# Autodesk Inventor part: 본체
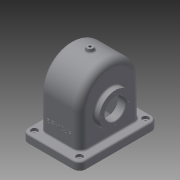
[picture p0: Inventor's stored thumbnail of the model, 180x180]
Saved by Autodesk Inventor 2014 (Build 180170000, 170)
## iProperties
Created: 2016-10
Part Number: 본체
Material: 일반
Document SubType Name: Modeling
Designer: USER
Density: 1 g/cm^3
Appearance: 기본값
Author: USER
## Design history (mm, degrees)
sketch "스케치1"
  geometry: L1 (43, -75)-(-43, -75); L2 (-55, -63)-(-55, 63); L3 (-43, 75)-(43, 75); L4 (55, 63)-(55, -63); L5 (55, -75)-(-55, 75); L6 (-55, -75)-(55, 75); A1 r 12 centre (-43, 63) between (-43, 75) and (-55, 63); A2 r 12 centre (43, 63) between (55, 63) and (43, 75); A3 r 12 centre (43, -63) between (43, -75) and (55, -63); A4 r 12 centre (-43, -63) between (-55, -63) and (-43, -75); 1 further point
  constraints: 12 end point, 8 point on circle, 8 point on line, 8 tangent, 4 centre point, 3 equal radius, 2 midpoint, 2 parallel, 1 horizontal, 1 perpendicular
  dimensions: "d0" = 110 distance of L5.end L6.end; "d1" = 150 distance of L6.end L5.start; "d2" = 12 radius of A1
extrude "돌출1" new body sketch "스케치1" distance "d3" = 15; taper "d4" = 0 deg
node "작업 평면1"
sketch "스케치2"
  geometry: L1 (0, -12)-(-15, -12) reference; L2 (-15, -12)-(-15, 138) reference; L3 (-15, 138)-(0, 138) reference; L4 (0, 138)-(0, -12) reference; L5 (-80, 5)-(-15, 5); L6 (-80, 121)-(-12.083, 121); L7 (-15, 5)-(-15, 121); C1 r 20 at (-65, 63); A1 r 58 centre (-80, 63) between (-80, 5) and (-80, 121); 2 further points
  constraints: 6 end point, 3 point on line, 2 centre point, 2 horizontal alignment, 2 perpendicular, 2 point on circle, 2 tangent, 1 midpoint
  dimensions: "d5" = 116 diameter of A1; "d6" = 80 distance of point (0, 63) A1.centre; "d7" = 40 diameter of C1; "d8" = 65 distance of point (0, 63) C1.centre
extrude "돌출2" join sketch "스케치2" stored distance "d9" = 77; taper "d10" = 0 deg
sketch "스케치3"
  geometry: L1 (0, -12)-(-15, -12) reference; L2 (-15, -12)-(-15, 5) reference; L3 (-15, 5)-(-80, 5) reference; L4 (-80, 121)-(-15, 121) reference; L5 (-15, 121)-(-15, 138) reference; L6 (-15, 138)-(0, 138) reference; L7 (0, 138)-(0, -12) reference; L8 (-80, 11)-(0, 11); L9 (0, 115)-(-80, 115); C1 r 20 at (-65, 63) reference; A1 r 58 centre (-80, 63) between (-80, 121) and (-80, 5) reference; A2 r 52 centre (-80, 63) between (-80, 115) and (-80, 11); 1 further point
  constraints: 4 end point, 2 point on circle, 2 point on line, 1 centre point
  dimensions: "d11" = 6 radial gap between concentric circles of A1 A2; "d12" = 104 distance between parallel lines of L9 L8; "d13" = 52 distance from line of C1.centre L9; "d14" = 80 distance of L9.start L9.end
extrude "돌출3" cut sketch "스케치3" stored distance "d15" = 67; taper "d16" = 0 deg
sketch "스케치4"
  geometry: C1 r 20 at (-65, 63) reference; C2 r 31 at (-65, 63); 1 further point
  constraints: 1 centre point, 1 coincident
  dimensions: "d17" = 62 diameter of C2
extrude "돌출4" join sketch "스케치4" distance "d18" = 10; taper "d19" = 0 deg
sketch "스케치5"
  geometry: C1 r 20 at (65, 63) reference; C2 r 37.5 at (65, 63); 1 further point
  constraints: 1 centre point, 1 coincident
  dimensions: "d20" = 75 diameter of C2
extrude "돌출5" join sketch "스케치5" distance "d21" = 5; taper "d22" = 0 deg
node "작업 평면2"
sketch "스케치6"
  geometry: L1 (-38.5, 138)-(38.5, 138) reference; L2 (38.5, 138)-(38.5, 102.5) reference; L3 (38.5, 102.5)-(43.5, 102.5) reference; L4 (43.5, 102.5)-(43.5, 85) reference; L5 (43.5, 85)-(33.5, 85) reference; L6 (33.5, 85)-(33.5, 132) reference; L7 (33.5, 132)-(-33.5, 132) reference; L8 (-33.5, 132)-(-33.5, 85) reference; L9 (-33.5, 85)-(-48.5, 85) reference; L10 (-48.5, 85)-(-48.5, 96) reference; L11 (-48.5, 96)-(-38.5, 96) reference; L12 (-38.5, 96)-(-38.5, 138) reference; L13 (-55, 0)-(-55, 15) reference; L14 (-55, 15)-(-38.5, 15) reference; L15 (-38.5, 15)-(-38.5, 34) reference; L16 (-38.5, 34)-(-48.5, 34) reference; L17 (-48.5, 34)-(-48.5, 45) reference; L18 (-48.5, 45)-(-33.5, 45) reference; L19 (-33.5, 45)-(-33.5, 0) reference; L20 (-33.5, 0)-(-55, 0) reference; L21 (55, 15)-(55, 0) reference; L22 (55, 0)-(33.5, 0) reference; L23 (33.5, 0)-(33.5, 45) reference; L24 (33.5, 45)-(43.5, 45) reference; L25 (43.5, 45)-(43.5, 27.5) reference; L26 (43.5, 27.5)-(38.5, 27.5) reference; L27 (38.5, 27.5)-(38.5, 15) reference; L28 (38.5, 15)-(55, 15) reference; L29 (43.5, 85)-(43.5, 45) reference; L30 (33.5, 85)-(33.5, 45) reference; L31 (43.5, 65)-(-28.801, 65); L32 (33.5, 104.747)-(19.5, 93); L33 (19.5, 93)-(19.5, 65); L34 (33.5, 104.747)-(33.5, 65); L35 (19.5, 65)-(33.5, 65); L36 (33.5, 85)-(19.5, 85); 1 further point
  constraints: 12 end point, 4 perpendicular, 4 point on line, 2 midpoint
  dimensions: "d24" = 56 diameter of L32.end L31; "d25" = 50 deg angle of L33 L32; "d26" = 24 distance between parallel lines of L29 L33
revolve "회전1" sketch "스케치6" stored, may be unused: angle "d27" = 90 deg
sketch "스케치7" dims "d28" = 52
  geometry: C1 r 20 at (0, 0) reference; C2 r 31 at (0, 0) reference; 6 further points
  constraints: 2 horizontal alignment, 1 coincident, 7 other
  dimensions: "d31" = 360 deg dimension on C1.centre point (-26, 0) (derived)
hole "구멍1" sketch "스케치7" at (-26, 0), (0, -26), (26, 0), (0, 26) diameter "d33" = 2.459; stored, may be unused: countersink angle "d37" = 90 deg, drill point angle "d39" = 118 deg; dims "d34" = 6, "d35" = 4, "d36" = 2, "d38" = 8
sketch "스케치8" dims "d40" = 58
  geometry: C1 r 20 at (0, 0) reference; C2 r 37.5 at (0, 0) reference; 6 further points
  constraints: 2 horizontal alignment, 1 coincident, 7 other
  dimensions: "d43" = 360 deg dimension on C1.centre point (29, 0) (derived)
hole "구멍2" sketch "스케치8" at (29, 0), (0, 29), (-29, 0), (0, -29) diameter "d45" = 2.459; stored, may be unused: countersink angle "d49" = 90 deg, drill point angle "d51" = 118 deg; dims "d46" = 6, "d47" = 4, "d48" = 2, "d50" = 8
sketch "스케치11"
  geometry: A1 r 12 centre (-43, -63) between (-55, -63) and (-43, -75) reference; A2 r 12 centre (43, -63) between (43, -75) and (55, -63) reference; A3 r 12 centre (43, 63) between (55, 63) and (43, 75) reference; A4 r 12 centre (-43, 63) between (-43, 75) and (-55, 63) reference; 5 further points
  constraints: 4 coincident
hole "구멍4" sketch "스케치11" at (-43, 63), (43, 63), (43, -63), (-43, -63) diameter "d64" = 5; stored, may be unused: countersink angle "d68" = 90 deg, drill point angle "d70" = 118 deg; dims "d65" = 40, "d66" = 12, "d67" = 5, "d69" = 50
fillet "모깎기1" dims "d71" = 8
fillet "모깎기2" dims "d72" = 13
sketch "스케치12"
  geometry: L1 (-48.5, 96)-(-38.5, 96) reference; L2 (-38.5, 96)-(-38.5, 125) reference; L3 (-25.5, 138)-(25.5, 138) reference; L4 (38.5, 125)-(38.5, 102.5) reference; L5 (38.5, 102.5)-(43.5, 102.5) reference; L6 (43.5, 102.5)-(43.5, 95.23) reference; L7 (43.5, 95.23)-(35.5, 95.23) reference; L8 (35.5, 95.23)-(34.761, 94) reference; L9 (34.761, 94)-(35.5, 92.771) reference; L10 (35.5, 92.771)-(43.5, 92.771) reference; L11 (43.5, 92.771)-(43.5, 85) reference; L12 (43.5, 85)-(19.5, 85) reference; L13 (19.5, 85)-(19.5, 93) reference; L14 (19.5, 93)-(33.5, 104.747) reference; L15 (33.5, 104.747)-(33.5, 124) reference; L16 (25.5, 132)-(-25.5, 132) reference; L17 (-33.5, 124)-(-33.5, 85) reference; L18 (-33.5, 85)-(-48.5, 85) reference; L19 (-48.5, 85)-(-48.5, 89.77) reference; L20 (-48.5, 89.77)-(-40.5, 89.77) reference; L21 (-40.5, 89.77)-(-39.761, 91) reference; L22 (-39.761, 91)-(-40.5, 92.229) reference; L23 (-40.5, 92.229)-(-48.5, 92.229) reference; L24 (-48.5, 92.229)-(-48.5, 96) reference; L25 (-55, 0)-(-55, 15) reference; L26 (-55, 15)-(-38.5, 15) reference; L27 (-38.5, 15)-(-38.5, 34) reference; L28 (-38.5, 34)-(-48.5, 34) reference; L29 (-48.5, 34)-(-48.5, 37.771) reference; L30 (-48.5, 37.771)-(-40.5, 37.771) reference; L31 (-40.5, 37.771)-(-39.761, 39) reference; L32 (-39.761, 39)-(-40.5, 40.23) reference; L33 (-40.5, 40.23)-(-48.5, 40.23) reference; L34 (-48.5, 40.23)-(-48.5, 45) reference; L35 (-48.5, 45)-(-33.5, 45) reference; L36 (-33.5, 45)-(-33.5, 0) reference; L37 (-33.5, 0)-(-55, 0) reference; L38 (55, 15)-(55, 0) reference; L39 (55, 0)-(33.5, 0) reference; L40 (33.5, 0)-(33.5, 25.253) reference; L41 (33.5, 25.253)-(19.5, 37) reference; L42 (19.5, 37)-(19.5, 45) reference; L43 (19.5, 45)-(43.5, 45) reference; L44 (43.5, 45)-(43.5, 37.229) reference; L45 (43.5, 37.229)-(35.5, 37.229) reference; L46 (35.5, 37.229)-(34.761, 36) reference; L47 (34.761, 36)-(35.5, 34.77) reference; L48 (35.5, 34.77)-(43.5, 34.77) reference; L49 (43.5, 34.77)-(43.5, 27.5) reference; L50 (43.5, 27.5)-(38.5, 27.5) reference; L51 (38.5, 27.5)-(38.5, 15) reference; L52 (38.5, 15)-(55, 15) reference; L53 (0, 132)-(0, 154.824); L54 (0, 144)-(-6, 144); L55 (-6, 144)-(-8.116, 132); L56 (0, 132)-(-8.116, 132); A1 r 13 centre (-25.5, 125) between (-25.5, 138) and (-38.5, 125) reference; A2 r 13 centre (25.5, 125) between (38.5, 125) and (25.5, 138) reference; A3 r 8 centre (25.5, 124) between (33.5, 124) and (25.5, 132) reference; A4 r 8 centre (-25.5, 124) between (-25.5, 132) and (-33.5, 124) reference; 1 further point
  constraints: 8 end point, 2 perpendicular, 2 point on line, 1 midpoint, 1 parallel
  dimensions: "d74" = 100 deg angle of L3 L55; "d75" = 6 distance from line of L53 L54.end; "d76" = 144 distance between parallel lines of L39 L54
revolve "회전3" sketch "스케치12" stored, may be unused: angle "d77" = 90 deg
fillet "모깎기3" dims "d78" = 3
chamfer "모따기1" distance "d79" = 1; stored, may be unused: second distance "d80" = 2, angle "d81" = 45 deg
sketch "스케치13"
  geometry: C1 r 6 at (0, 0) reference; 1 further point
  constraints: 1 coincident
hole "구멍5" sketch "스케치13" at (0, 0) diameter "d82" = 4.459; stored, may be unused: countersink angle "d86" = 90 deg, drill point angle "d88" = 118 deg; dims "d83" = 40, "d84" = 12, "d85" = 5, "d87" = 50
node "작업 평면3"
sketch "스케치14" dims "d0" = 110, "d1" = 150, "d2" = 12
  geometry: L1 (-29.5, -80)-(-29.5, -68) reference; L2 (-17.5, -80)-(68.5, -80) reference; L3 (-13, 0)-(-13, -62) reference; L4 (64, -62)-(64, 0) reference; 2 further points
  constraints: 1 other
  dimensions: "d90" = 40 distance from line of L2 point (25.5, -40); "d91" = 38.5 distance from line of L3 point (25.5, -40)
feature "엠보싱1" sketch "스케치14" dims "d0" = 110, "d1" = 150, "d2" = 12, "d92" = 0.5, "d93" = 0
node "솔리드1"
node "투영된 루프1"
node "절단 모서리 투영1"
node "절단 모서리 투영2"
node "절단 모서리 투영3"
node "절단 모서리 투영5"
other parameters: "d23" = 0, "d89" = 0.5
